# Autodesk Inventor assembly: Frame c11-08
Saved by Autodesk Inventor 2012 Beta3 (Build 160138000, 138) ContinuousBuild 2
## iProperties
Created: 2011-01
Part Number: Frame c11-08
Document SubType Name: Assembly
Designer: Beta-8540w
_FrameDoc: Frame Assembly
_Version: 15.0.0
Author: Beta-8540w
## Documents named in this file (20)
- C:\Inventor 2012 Essentials\Assemblies\Chapter 11\Frame\Frame c11-08.iam
- C:\Inventor 2012 Essentials\Assemblies\Chapter 11\Frame\Skeleton-c11-08.ipt
- C:\Inventor 2012 Essentials\Assemblies\Chapter 11\Frame\ANSI 3x3x3_16 00000037.ipt
- ANSI 3x3x3_16 00000037.ipt
- C:\Inventor 2012 Essentials\Assemblies\Chapter 11\Frame\ANSI 3x3x3_16 00000038.ipt
- ANSI 3x3x3_16 00000038.ipt
- C:\Inventor 2012 Essentials\Assemblies\Chapter 11\Frame\ANSI 3x3x3_16 00000039.ipt
- ANSI 3x3x3_16 00000039.ipt
- C:\Inventor 2012 Essentials\Assemblies\Chapter 11\Frame\ANSI 3x3x3_16 00000040.ipt
- ANSI 3x3x3_16 00000040.ipt
- C:\Inventor 2012 Essentials\Assemblies\Chapter 11\Frame\ANSI 3x3x3_16 00000041.ipt
- ANSI 3x3x3_16 00000041.ipt
- C:\Inventor 2012 Essentials\Assemblies\Chapter 11\Frame\ANSI 3x3x3_16 00000042.ipt
- ANSI 3x3x3_16 00000042.ipt
- C:\Inventor 2012 Essentials\Assemblies\Chapter 11\Frame\ANSI 2 1_4x5_16 00000043.ipt
- ANSI 2 1_4x5_16 00000043.ipt
- C:\Inventor 2012 Essentials\Assemblies\Chapter 11\Frame\ANSI L 1.5 x 1.5 x 3_16 00000044.ipt
- ANSI L 1.5 x 1.5 x 3_16 00000044.ipt
- C:\Inventor 2012 Essentials\Assemblies\Chapter 11\Frame\ANSI L 1.5 x 1.5 x 3_16 00000045.ipt
- ANSI L 1.5 x 1.5 x 3_16 00000045.ipt
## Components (10 placed, 10 different names)
1. Frame Reference Model
2. ANSI 3x3x3_16 00000037:1
3. ANSI 3x3x3_16 00000038:1
4. ANSI 3x3x3_16 00000039:1
5. ANSI 3x3x3_16 00000040:1
6. ANSI 3x3x3_16 00000041:1
7. ANSI 3x3x3_16 00000042:1
8. ANSI 2 1_4x5_16 00000043:1
9. ANSI L 1.5 x 1.5 x 3_16 00000044:1
10. ANSI L 1.5 x 1.5 x 3_16 00000045:1
